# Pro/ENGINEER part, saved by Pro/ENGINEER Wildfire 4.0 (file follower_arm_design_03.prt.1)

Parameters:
  METRIC = "NO"

Other parameters: PITCH, DRILL_DIAMETER, THREAD_DIAMETER, THREADS_PER_INCH, THREAD_DEPTH, THREAD_LENGTH, DRILL_POINT_ANGLE, DRILL_DEPTH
